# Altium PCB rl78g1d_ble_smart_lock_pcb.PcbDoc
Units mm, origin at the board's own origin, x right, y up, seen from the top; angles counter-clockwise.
Board outline 77.6 x 48.9 mm, 2 copper layers (Top Layer, Bottom Layer); 55 components, 39 nets, 175 pads, 18 vias.
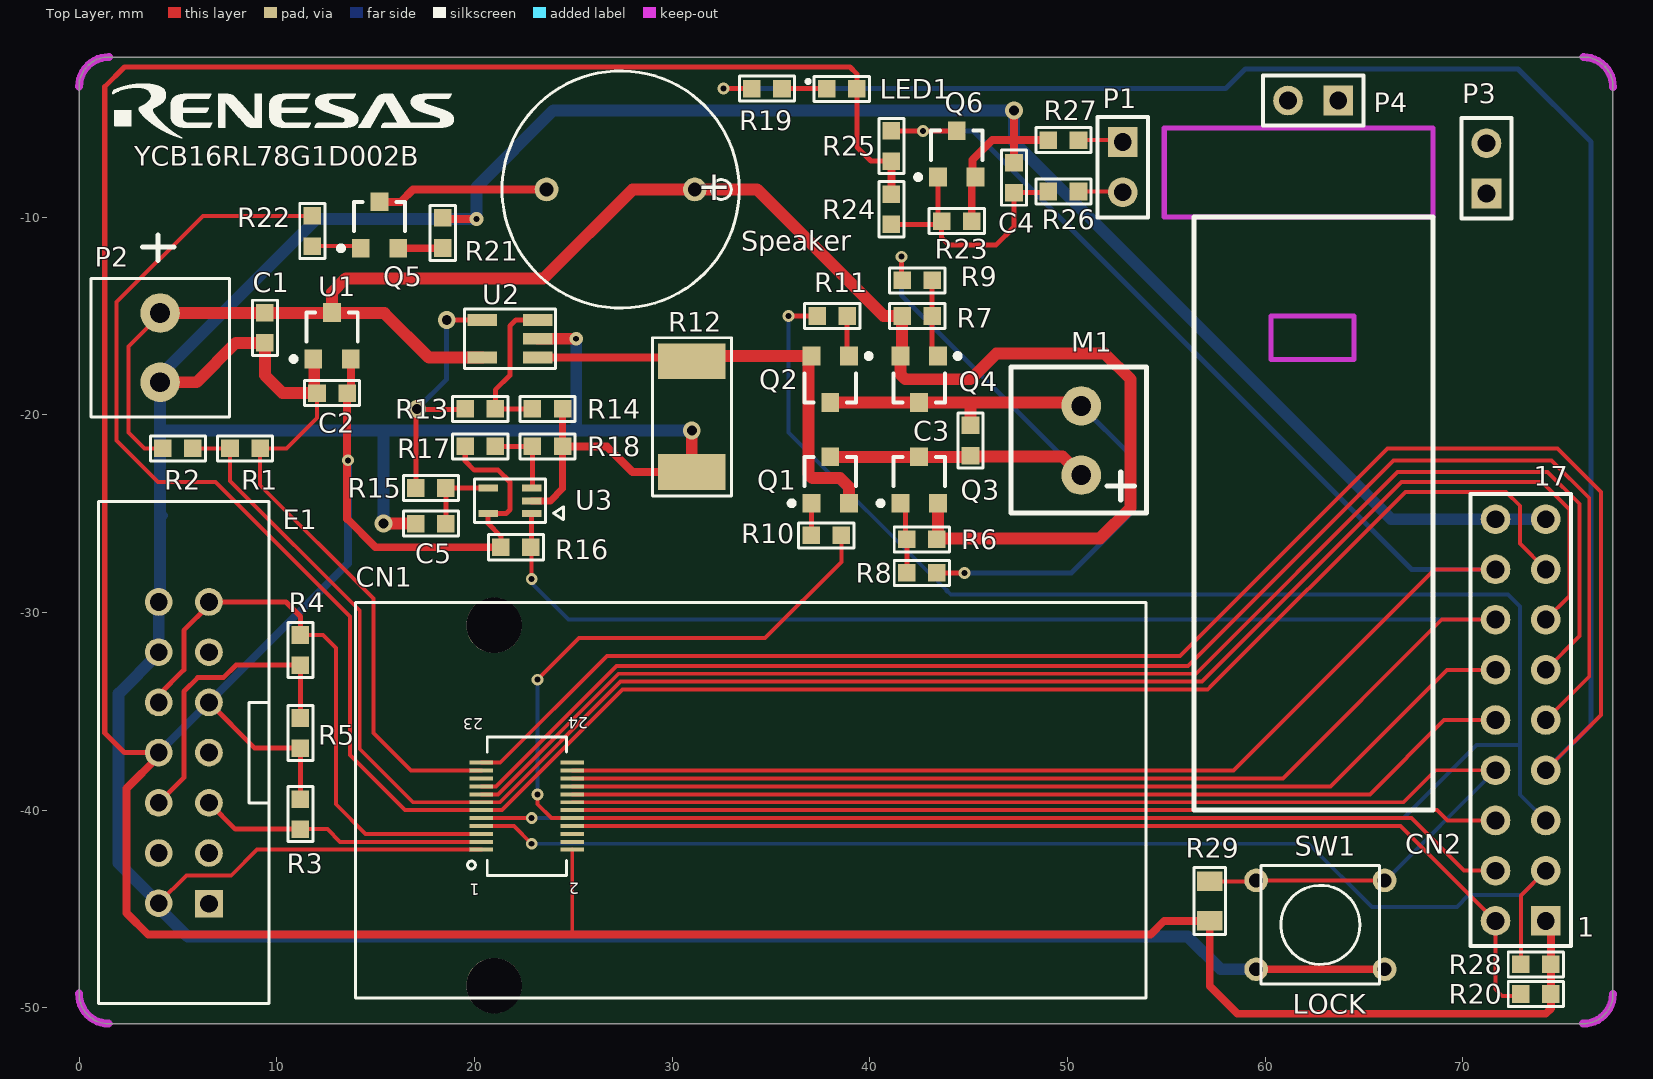
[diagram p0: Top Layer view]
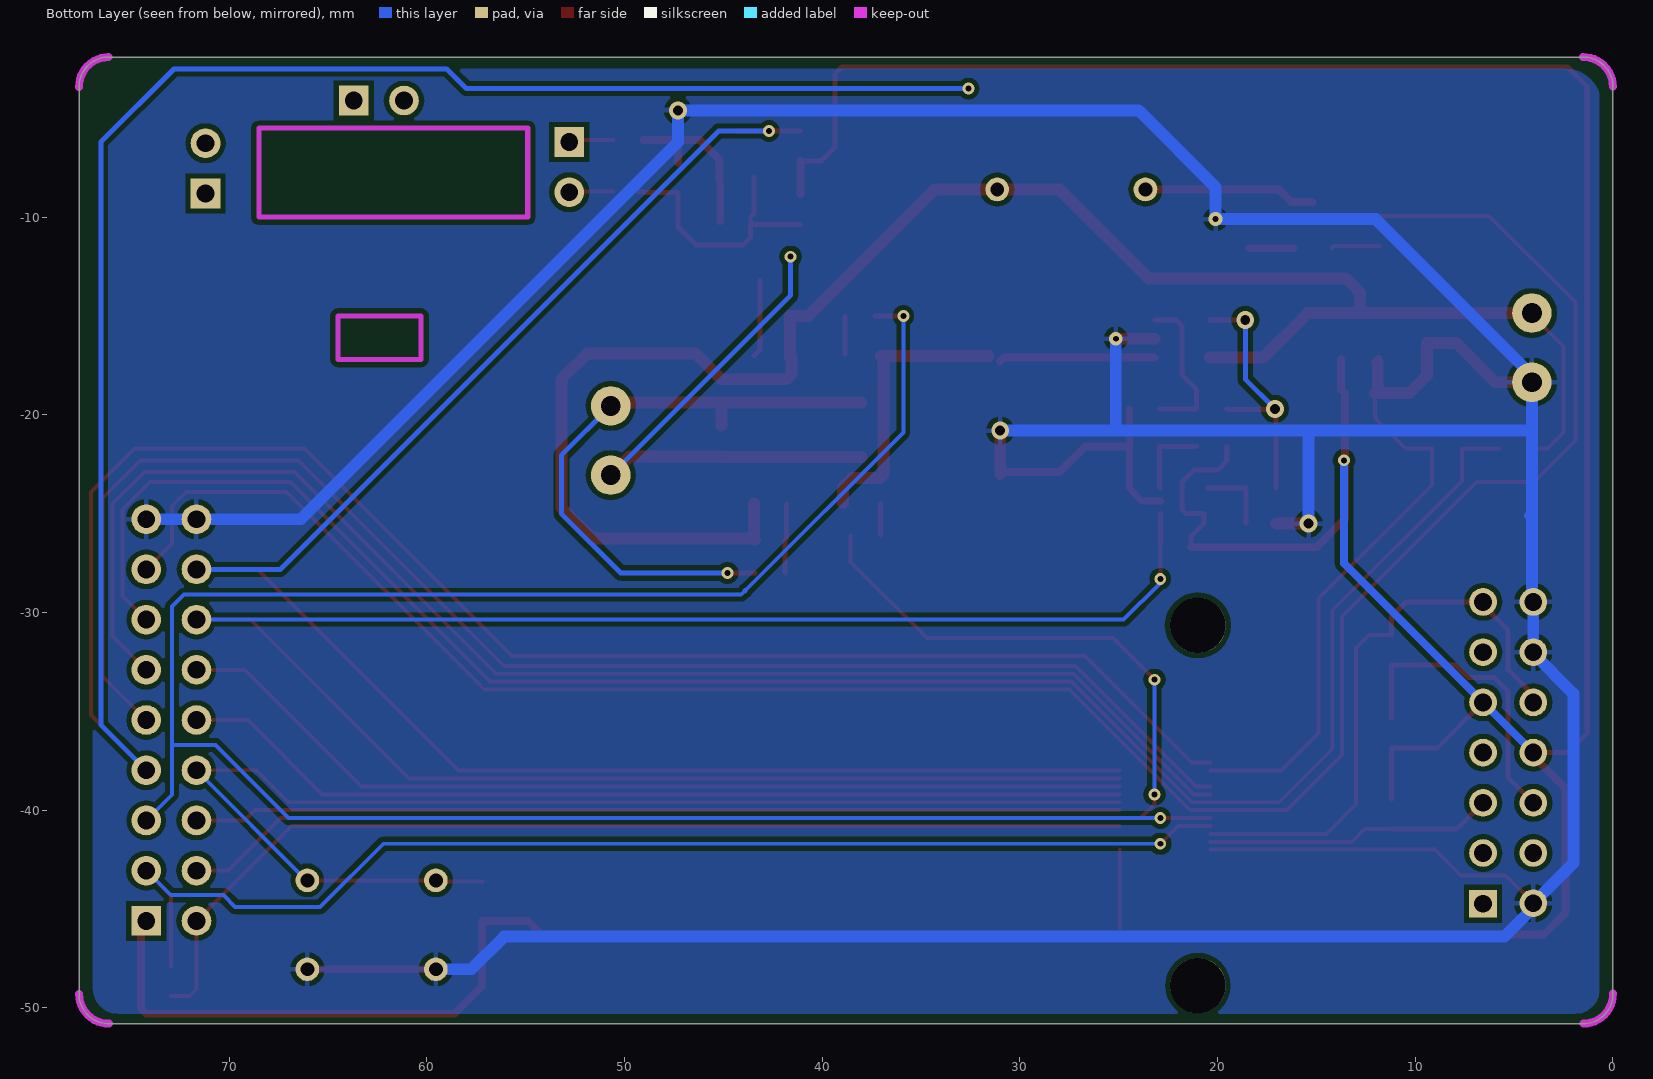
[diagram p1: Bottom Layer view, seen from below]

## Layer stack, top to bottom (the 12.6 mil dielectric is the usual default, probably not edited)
Top Layer: signal copper 0.0356
Dielectric: dielectric 0.32, FR-4, Dk 4.8
Bottom Layer: signal copper 0.0356

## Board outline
1.5,-50.8 cw(c1.5,-49.3) 0,-49.277 0,-3.4 cw(c1.5,-3.4) 1.523,-1.9 76.1,-1.9 cw(c76.1,-3.4) 77.6,-3.423 77.6,-3.4 77.6,-49.3 cw(c76.1,-49.3) 76.077,-50.8

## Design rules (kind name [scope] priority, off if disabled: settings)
Clearance [All] p1: gap=0.254
ComponentClearance [All] p1: gap=0.254 collisioncheckmode=3 verticalgap=0.254
PolygonConnect [All] p1: connectstyle=Relief reliefconductorwidth=0.254 reliefentries=4 polygonreliefangle="90 Angle"
RoutingVias [All] p1: holewidth=0.711 width=1.27 viastyle="Through Hole" minholewidth=0.711 minwidth=1.27 maxholewidth=0.711 maxwidth=1.27
SolderMaskExpansion [All] p1: expansion=0.102
TestPointUsage [All] p1: valid=0 allowmultiple=FALSE
Testpoint [All] p1: side=15 testpointundercomponent=TRUE minsize=1.016 maxsize=2.54 preferedsize=1.524 minholesize=0 maxholesize=1.016 preferedholesize=0.813 testpointgrid=0.025 style=1023 order=0123456789
Width [All] p1: maxlimit=1 minlimit=0.2 preferedwidth=0.254 minimp=50.000000 maximp=50.000000 favimp=50.000000
18 further rules are at their usual default settings.

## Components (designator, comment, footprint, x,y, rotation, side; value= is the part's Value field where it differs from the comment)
C1 "1uF" 0603 9.4,-15.6 r270 top
C2 "1uF" 0603 12.8,-18.9 r180 top
C3 "100nF" 0603 45.1,-21.3 r90 top
C4 "100nF" 0603 47.3,-8 r270 top
C5 "100nF" 0603 17.8,-25.5 r0 top
CN1 "Coaxial connector" "CRS5001 - 24" 14,-49.5 r180 top
CN2 "Header 9X2" HDR2X9 74.2,-45.6 r90 top
E1 "J1" "E8 Connect - duplicate" 5.3,-37.1 r180 top
LED1 "R" "LED 0603" 38.586,-3.51 r180 top
M1 "Motor" "CON-2 D" 50.7,-21.3 r90 top
P1 "LOCK" HDR1X2 52.8,-6.2 r270 top
P2 "BAT AAAx3" "CON-2 D" 4.1,-16.6 r270 top
P3 "Baffle" HDR1X2 71.2,-8.8 r90 top
P4 "Baffle" HDR1X2 63.7,-4.1 r180 top
Q1 "S8050" SOT23A 38,-23.3 r0 top
Q2 "S8050" SOT23A 38,-18.2 r180 top
Q3 "S8550" SOT23A 42.5,-23.3 r0 top
Q4 "S8550" SOT23A 42.5,-18.2 r180 top
Q5 "S8050" SOT23A 15.2,-10.4 r0 top
Q6 "S8050" SOT23A 44.4,-6.8 r0 top
R1 "100K" 0603 8.4,-21.7 r0 top
R2 "100K" 0603 5,-21.7 r0 top
R3 "1K" 0603 11.2,-40.2 r270 top
R4 "10K" 0603 11.2,-31.9 r270 top
R5 "1K" 0603 11.2,-36.1 r270 top
R6 "4.7K" 0603 42.638,-26.3 r0 top
R7 "4.7K" 0603 42.4,-15 r180 top
R8 "470" 0603 42.638,-28 r180 top
R9 "470" 0603 42.4,-13.2 r180 top
R10 "470" 0603 37.8,-26.1 r180 top
R11 "470" 0603 38.1,-15 r180 top
R12 "1.5R" 2512 31,-20.1 r90 top
R13 "10K" 0603 20.3,-19.7 r180 top
R14 "1K" 0603 23.7,-19.7 r180 top
R15 "1K" 0603 17.8,-23.7 r0 top
R16 "1K" 0603 22.1,-26.7 r180 top
R17 "100K" 0603 20.3,-21.6 r0 top
R18 "100K" 0603 23.7,-21.6 r0 top
R19 "1K" 0603 34.8,-3.5 r180 top
R20 "1K" 0603 73.7,-49.3 r180 top
R21 "100" 0603 18.4,-10.8 r270 top
R22 "10K" 0603 11.8,-10.7 r90 top
R23 "1M" 0603 44.4,-10.2 r0 top
R24 "470K" 0603 41.1,-9.6 r270 top
R25 "2.2M" 0603 41.1,-6.4 r90 top
R26 "10K" 0603 49.8,-8.7 r0 top
R27 "100" 0603 49.8,-6.1 r180 top
R28 "1K" 0603 73.7,-47.8 r0 top
R29 "10K" 0805 57.2,-44.6 r90 top
Speaker "Buzzer" "BUZZER A" 27.4,-8.6 r180 top
SW1 "LOCK" "KEY B (6 X 6)" 62.8,-45.8 r180 top
U1 "XC6206-3.3V" SOT23A 12.8,-16 r0 top
U2 "LM321" SOT-23-5 23.2,-17.1 r180 top
U3 "NCX2202" "SC-70 5" 22.9,-25 r180 top
YCB16RL78G1D002B "Comment" "RENESAS LOGO" 9.9,-4.8 r0 top

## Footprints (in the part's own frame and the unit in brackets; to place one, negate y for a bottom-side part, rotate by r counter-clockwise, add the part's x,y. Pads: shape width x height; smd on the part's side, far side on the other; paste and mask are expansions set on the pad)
0603 [mil]
  rect 35x35 smd: 1(-30,0) 2(30,0)
  silkscreen extent -55,-25 55,25
0805 [mm]
  rect 1x1.3 smd: 1(-1,0) 2(1,0)
  silkscreen extent -1.7,-0.8 1.7,0.8
2512 [mm]
  rect 1.8x3.4 smd: 1(-2.794,0) 2(2.806,0)
  silkscreen extent -4,-2 4,2
"BUZZER A" [mm]
  round 1.2 hole 0.7: 1(-3.75,0) 2(3.75,0)
  silkscreen extent -6,-6 6,6
"CON-2 D" [mm]
  round 2 hole 1: 1(-1.75,0) 2(1.75,0)
  silkscreen extent -3.65,-3.3 3.71,3.56
"CRS5001 - 24" [mm]
  round 2.8 hole 2.8: 0(-7,-0.625) 0(-7,-18.85)
  rect 1.2x0.2 smd: 1(-6.35,-7.5) 2(-10.95,-7.5) 3(-6.35,-7.9) 4(-10.95,-7.9) 5(-6.35,-8.3) 6(-10.95,-8.3) 7(-6.35,-8.7) 8(-10.95,-8.7) 9(-6.35,-9.1) 10(-10.95,-9.1) 11(-6.35,-9.5) 12(-10.95,-9.5) 13(-6.35,-9.9) 14(-10.95,-9.9) 15(-6.35,-10.3) 16(-10.95,-10.3) 17(-6.35,-10.7) 18(-10.95,-10.7) 19(-6.35,-11.1) 20(-10.95,-11.1) 21(-6.35,-11.5) 22(-10.95,-11.5) 23(-6.35,-11.9) 24(-10.95,-11.9)
  silkscreen extent -39.98,-20 0.03,0
"E8 Connect - duplicate" [mm]
  rect 1.4x1.4 hole 0.9: 1(-1.27,7.633)
  round 1.4 hole 0.9: 2(1.27,7.607) 3(-1.27,5.067) 4(1.27,5.067) 5(-1.27,2.527) 6(1.27,2.527) 7(-1.27,-0.013) 8(1.27,-0.013) 9(-1.27,-2.553) 10(1.27,-2.553) 11(-1.27,-5.093) 12(1.27,-5.093) 13(-1.27,-7.633) 14(1.27,-7.633)
  silkscreen extent -4.32,-12.71 4.32,12.69
HDR1X2 [mm] "Connector; Header; 2 Position"
  rect 1.5x1.5 hole 0.9: 1(0,0)
  round 1.5 hole 0.9: 2(2.54,0)
  silkscreen extent -1.27,-1.27 3.81,1.27
HDR2X9 [mm] "Connector; Header; 9x2 Position"
  rect 1.5x1.5 hole 0.9: 1(0,0)
  round 1.5 hole 0.9: 2(0,2.54) 3(2.54,0) 4(2.54,2.54) 5(5.08,0) 6(5.08,2.54) 7(7.62,0) 8(7.62,2.54) 9(10.16,0) 10(10.16,2.54) 11(12.7,0) 12(12.7,2.54) 13(15.24,0) 14(15.24,2.54) 15(17.78,0) 16(17.78,2.54) 17(20.32,0) 18(20.32,2.54)
  silkscreen extent -1.27,-1.27 21.59,3.81
"KEY B (6 X 6)" [mm]
  round 1.2 hole 0.7: 1(-3.25,2.25) 2(-3.25,-2.25) 3(3.25,-2.25) 4(3.25,2.25)
  silkscreen extent -3,-3 3,3
"LED 0603" [mil]
  rect 35x35 smd: A(-30,0) K(30,0)
  silkscreen extent -55,-25 69,25
"RENESAS LOGO" [mm]
  silkscreen extent -8.18,-1.18 9.06,1.54
"SC-70 5" [mm]
  rect 1x0.35 smd: 1(0,0) 2(0,-0.65) 3(0,-1.3) 4(2.2,-1.3) 5(2.2,0)
  silkscreen extent -1.6,-1.75 2.9,0.45
SOT23A [mm] "SOT-23; 3 Leads; Body 3.0 x 2.5 mm, inc. leads (LxW max)"
  rect 0.9x0.95 smd: 1(-0.95,-1.175) 2(0.95,-1.175) 3(0,1.175)
  silkscreen extent -2.07,-1.3 1.3,1.18
SOT-23-5 [mm]
  rect 1.5x0.6 smd: 1(0,0) 2(0,-0.95) 3(0,-1.9) 4(2.8,-1.9) 5(2.8,0)
  silkscreen extent -0.9,-2.45 3.7,0.55

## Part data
C1 C2 C3 C4 C5: library part CAP
CN2: "Header, 9-Pin, Dual row"
E1: library part E1
LED1: library part LED2, "Typical RED, GREEN, YELLOW, AMBER GaAs LED"
P1: "Header, 4-Pin"
P2: library part "Cell Battery", "Header, 4-Pin"
P3 P4: library part Header-2, "Header, 4-Pin"
R1 R2 R3 R4 R5 R6 R7 R8 R9 R10 R11 R12 R13 R14 R15 R16 R17 R18 R19 R20 R21 R22 R23 R24 R25 R26 R27 R28 R29: library part RES
Speaker: library part SPEAKER
SW1: library part SW-PB, "Switch"
U1: library part XC6206

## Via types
v1: diameter 0.6, hole 0.3, Top Layer to Bottom Layer, 11 vias
v2: diameter 0.9, hole 0.5, Top Layer to Bottom Layer, 5 vias
v3: diameter 0.7, hole 0.3, Top Layer to Bottom Layer, 2 vias

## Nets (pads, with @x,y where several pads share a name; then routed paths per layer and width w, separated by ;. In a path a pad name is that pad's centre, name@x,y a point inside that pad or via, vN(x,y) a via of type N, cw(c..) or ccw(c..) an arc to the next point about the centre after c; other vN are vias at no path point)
3.3V: C2.1 CN1.2 CN2.1 E1.8 E1.9 LED1.A R3.1 R5.2 R16.2 R17.1 R20.1 R24.1 R25.1 R28.2 R29.1 U1.2 U3.5 | length 227.3
  Top Layer w0.2: CN1.2 24.95,-46.25 25,-46.3
  Top Layer w0.254: E1.8 2.287,-37.087 1.3,-36.1 1.3,-3.4 2.3,-2.4 39,-2.4 39.348,-2.748 39.348,-6.448 40.062,-7.162 R25.1 ; E1.9 8.885,-36.862 R5.2 R3.1 ; R17.1 19.538,-22.338 20,-22.8 21.2,-22.8 21.8,-23.4 21.8,-24.8 21.6,-25 U3.5 20.7,-25.5 21.338,-26.138 R16.2
  Top Layer w0.4: E1.8 4.03,-37.27 2.4,-38.9 2.4,-45.2 3.5,-46.3 54.2,-46.3 54.9,-45.6 R29.1 57.2,-48.9 58.6,-50.3 74.2,-50.3 74.462,-50.038 CN2.1@74.462,-45.638 ; C2.1 13.562,-25.262 15,-26.7 R16.2 ; C2.1@13.75,-18.712 U1.2 ; R24.1 R25.1
  Bottom Layer w0.4: E1.8 13.6,-27.517 v1(13.6,-22.3)
4.5V: C1.1 P2.1 Q3.2 Q4.2 R2.1 R6.2 R7.2 Speaker.1 U1.3 U2.5 | length 95.3
  Top Layer w0.2: P2.1@4.2,-14.85 2.5,-16.55 2.5,-20.9 3.3,-21.7 R2.1
  Top Layer w0.6: P2.1@4.2,-14.85 15.45,-14.85 17.7,-17.1 U2.5 ; U1.3@12.775,-14.85 U1.3 12.8,-13.8 13.5,-13.1 23.5,-13.1 28,-8.6 34.3,-8.6 40.7,-15 R7.2 Q4.2@41.638,-17.138 ; Q4.2 41.55,-17.95 41.8,-18.2 45.1,-18.2 46.4,-16.9 51.9,-16.9 53.2,-18.2 53.2,-24.7 51.65,-26.25 R6.2@43.45,-26.25 ; R6.2 R6.2@43.45,-26.25 ; Q3.2 R6.2@43.45,-26.25
AD1: CN1.13 CN2.13 R1.1 R2.2 | length 95.5
  Top Layer w0.2: R2.2 R1.1 7.638,-23.338 14.2,-29.9 14.2,-36.9 16.9,-39.6 21.3,-39.6 27.4,-33.5 56.8,-33.5 57.3,-33 66.9,-23.4 74,-23.4 75.4,-24.8 75.4,-29.16 CN2.13
BUZZER: CN1.11 CN2.15 R22.2 | length 112.3
  Top Layer w0.2: R22.2 6.262,-9.938 1.9,-14.3 1.9,-21.3 4,-23.4 6.9,-23.4 13.7,-30.2 13.7,-37.2 16.5,-40 21.4,-40 27.5,-33.9 57.1,-33.9 57.3,-33.7 67.1,-23.9 72.2,-23.9 72.9,-24.6 72.9,-26.52 CN2.15
CCW: CN1.10 CN2.4 R10.1 | length 75.3
  Top Layer w0.2: v1(23.2,-39.2) 23.2,-39.7 23.9,-40.4 67.4,-40.4 70.06,-43.06 CN2.4 ; v1(23.2,-33.4) 25.3,-31.3 34.7,-31.3 38.562,-27.438 R10.1
  Bottom Layer w0.2: v1(23.2,-39.2) v1(23.2,-33.4)
CN1: CN1.15 CN2.11 | length 72.1
  Top Layer w0.2: CN1.15 21.2,-39.2 27.3,-33.1 56.5,-33.1 66.7,-22.9 74.3,-22.9 75.9,-24.5 75.9,-31.2 CN2.11
CN2: CN1.17 CN2.9 | length 75.8
  Top Layer w0.2: CN1.17 21.1,-38.8 27.2,-32.7 56.1,-32.7 66.5,-22.3 74.5,-22.3 76.4,-24.2 76.4,-33.24 CN2.9
CW: CN1.9 CN2.5 R11.2 | length 113.4
  Top Layer w0.2: CN1.9 v1(22.9,-40.4)
  Top Layer w0.254: v1(35.9,-15) R11.2
  Bottom Layer w0.2: v1(22.9,-40.4) 67,-40.4 70.7,-36.7 72.9,-36.7 ; v1(35.9,-15) 35.9,-20.9 43.9,-28.9 44.1,-29.1 72.3,-29.1 72.9,-29.7 72.9,-39.22 CN2.5
GND: C1.2 C2.2 C4.1 C5.1 CN1.1 CN1.21 CN2.17 CN2.18 E1.2 E1.12 E1.14 P2.2 Q6.2 R1.2 R12.1 R14.1 R18.2 R21.1 R23.2 R27.2 SW1.1 SW1.4 U1.1 U2.2 U3.2 | length 302.8
  Top Layer w0.2: E1.2 5.437,-43.3 7.7,-43.3 9,-42 CN1.1 ; C2.2 12.038,-20.162 10.5,-21.7 R1.2 9.162,-23.562 14.9,-29.3 14.9,-36.1 16.8,-38 CN1.21
  Top Layer w0.35: U3.2 23.85,-24.35 24.462,-23.738 R14.1
  Top Layer w0.4: U1.1 U1.1@12.038,-17.363 ; R21.1@18.462,-10.1 v3(20.1,-10.1) ; R18.2 26.7,-21.6 27.994,-22.894 R12.1 ; R23.2 45.162,-8.163 45.2,-8.125 45.2,-7.1 46.2,-6.1 R27.2 ; C4.1 47.3,-6.1 ; v2(47.3,-4.6) 47.3,-6 47.4,-6.1 ; SW1.4 SW1.1
  Top Layer w0.6: P2.2@4.2,-18.35 5.95,-18.35 7.938,-16.362 C1.2 9.4,-18 10.3,-18.9 C2.2 ; C2.2@11.9,-18.9 U1.1@11.9,-17.301 ; v2(15.4,-25.5) C5.1 ; U2.2 v3(25.15,-16.15) ; R12.1@31,-23 v2(31,-20.8)
  Bottom Layer w0.4: 4.1,-25.3 4.3,-25.1 ; P2.2 P2.2@4.1,-18
  Bottom Layer w0.6: 4.1,-20.7 4.2,-20.8 v2(31,-20.8) ; P2.2 4.1,-29.397 E1.14 4.03,-32.07 2,-34.1 2,-42.677 E1.2 4.03,-44.93 5.5,-46.4 56.1,-46.4 57.75,-48.05 SW1.4 ; P2.2@4.1,-18 12,-10.1 v3(20.1,-10.1) 20.1,-8.5 24,-4.6 v2@47.4,-4.6 ; v2(15.4,-25.5) 15.4,-20.8 ; 25.15,-20.75 v3(25.15,-16.15) ; v2(47.3,-4.6) 47.3,-6.2 66.38,-25.28 CN2.17
IN-: C5.2 R15.2 U3.4 | length 3.7
  Top Layer w0.254: C5.2 R15.2 U3.4@20.5,-23.7
LED1: CN1.23 CN2.7 R19.2 | length 159.4
  Top Layer w0.2: CN1.23 21.3,-37.6 26.7,-32.2 55.7,-32.2 64.7,-23.2 66.2,-21.7 74.8,-21.7 77,-23.9 77,-35.18 CN2.7
  Top Layer w0.254: v1(32.6,-3.5) R19.2
  Bottom Layer w0.254: v1(32.6,-3.5) 58,-3.5 59,-2.5 72.8,-2.5 76.5,-6.2 76.5,-35.68 CN2.7
M+: C3.1 M1.1 Q1.3 Q3.3 R9.2 | length 29.1
  Top Layer w0.254: R9.2@41.6,-13.162 v1(41.6,-12)
  Top Layer w0.6: Q1.3 45.037,-22.125 45.062,-22.1 49.75,-22.1 M1.1
  Bottom Layer w0.254: v1(41.6,-12) 41.6,-13.95 M1.1
M-: C3.2 M1.2 Q2.3 Q4.3 R8.1 | length 31.5
  Top Layer w0.254: R8.1 v1(44.8,-28)
  Top Layer w0.6: Q2.3 50.525,-19.375 M1.2 ; C3.2 45.1,-19.375
  Bottom Layer w0.254: v1(44.8,-28) 50.2,-28 53.2,-25 53.2,-22.05 M1.2
NetC4_2: C4.2 Q6.1 R23.1 R24.2 R26.1 | length 13.5
  Top Layer w0.254: R24.2 R23.1@43.662,-10.362 ; Q6.1 43.45,-9.812 R23.1@43.638,-10 ; R23.1 43.638,-11.038 44,-11.4 46.4,-11.4 47.3,-10.5 C4.2 48.976,-8.762 R26.1 R26.1@49.338,-8.7
NetE1_6: E1.6 R4.2 R5.1 | length 15.3
  Top Layer w0.254: E1.6 5.3,-38.357 5.3,-34 6,-33.3 7.3,-33.3 7.938,-32.662 R4.2 R5.1
NetLED1_K: LED1.K R19.1 | length 2.3
  Top Layer w0.254: R19.1 LED1.K@37.814,-3.5
NetP1_1: P1.1 R27.1 | length 2.1
  Top Layer w0.2: R27.1 P1.1@52.7,-6.1
NetP1_2: P1.2 R26.2 | length 2.2
  Top Layer w0.2: R26.2 P1.2@52.76,-8.7
NetQ1_1: Q1.1 R10.2 | length 1.6
  Top Layer w0.254: R10.2@37.05,-26.088 Q1.1
NetQ2_1: Q2.1 R11.1 | length 1.9
  Top Layer w0.254: Q2.1@38.862,-16.937 R11.1
NetQ3_1: Q3.1 R6.1 R8.2 | length 3.5
  Top Layer w0.254: Q3.1@41.8,-24.5 41.8,-26.224 R6.1 R8.2
NetQ4_1: Q4.1 R7.1 R9.1 | length 3.9
  Top Layer w0.254: R9.1 43.162,-16.737 Q4.1
NetQ5_1: Q5.1 R22.1 | length 2.5
  Top Layer w0.2: R22.1 14.137,-11.462 Q5.1
NetQ5_2: Q5.2 R21.2 | length 2.2
  Top Layer w0.4: Q5.2 R21.2@18.387,-11.575
NetQ5_3: Q5.3 Speaker.2 | length 8.7
  Top Layer w0.4: Q5.3 16.275,-9.225 16.9,-8.6 Speaker.2
NetR13_1: R13.1 R14.2 U2.3 | length 7.9
  Top Layer w0.254: R14.2 R13.1 21.062,-18.738 21.8,-18 21.8,-15.5 22.1,-15.2 U2.3
NetR13_2: R13.2 R15.1 U2.4 | length 13.4
  Top Layer w0.254: R15.1 17.038,-19.762 v2(17.1,-19.7) ; v2@17.138,-19.738 19.5,-19.738 R13.2 ; v2(18.6,-15.2) U2.4
  Bottom Layer w0.254: v2(17.1,-19.7) 18.6,-18.2 v2(18.6,-15.2)
NetR17_2: R17.2 R18.1 U3.3 | length 4
  Top Layer w0.254: R17.2 R18.1 22.938,-23.662 U3.3
P10: CN1.14 CN2.8 R29.2 SW1.2 SW1.3 | length 64.1
  Top Layer w0.2: CN1.14 67,-39.6 68.62,-37.98 CN2.8 ; R29.2 SW1.3@59.5,-43.6 ; SW1.3 SW1.2
  Bottom Layer w0.2: SW1.2 66.09,-43.55 CN2.8
P12: CN1.12 CN2.6 | length 46.9
  Top Layer w0.2: CN1.12 68.7,-40 69.22,-40.52 CN2.6
P16/INTP5: CN1.20 CN2.14 R16.1 U3.1 | length 103.1
  Top Layer w0.2: v1(22.9,-28.3) R16.1@22.9,-26.5 ; CN1.20 60.9,-38.4 68.94,-30.36 CN2.14
  Top Layer w0.254: R16.1@22.9,-26.5 U3.1
  Bottom Layer w0.2: v1(22.9,-28.3) 22.9,-28.5 24.76,-30.36 CN2.14
P22: CN1.16 CN2.10 | length 48.3
  Top Layer w0.2: CN1.16 65.3,-39.2 69.06,-35.44 CN2.10
P23: CN1.18 CN2.12 | length 49.2
  Top Layer w0.2: CN1.18 63.3,-38.8 69.2,-32.9 CN2.12
P30/INTP3: CN1.22 CN2.16 Q6.3 R25.2 | length 92.4
  Top Layer w0.2: CN1.22 58.4,-38 68.58,-27.82 CN2.16
  Top Layer w0.254: R25.2 Q6.3@44.387,-5.638
  Bottom Layer w0.254: v1(42.7,-5.638) 45.238,-5.638 67.42,-27.82 CN2.16
P40/TOOL0: CN1.3 E1.5 R3.2 | length 14.6
  Top Layer w0.2: R3.2 12.562,-40.962 13.2,-41.6 CN1.3
  Top Layer w0.254: E1.5 7.905,-40.962 R3.2
P60: CN1.7 CN2.3 R28.1 | length 61.7
  Top Layer w0.2: CN1.7 22,-40.8 v1(22.9,-41.7) ; R28.1@72.938,-47.9 72.938,-44.322 CN2.3
  Bottom Layer w0.2: v1(22.9,-41.7) 62.2,-41.7 65.4,-44.9 69.7,-44.9 70.3,-44.3 72.96,-44.3 CN2.3
P61: CN1.8 CN2.2 R20.2 | length 53.6
  Top Layer w0.2: CN1.8 66.86,-40.8 CN2.2 71.66,-49.06 72,-49.4 R20.2@72.938,-49.4
RESET: CN1.5 E1.10 E1.13 R4.1 | length 29.9
  Top Layer w0.2: R4.1 12.338,-31.138 13,-31.8 13,-39.7 14.5,-41.2 CN1.5
  Top Layer w0.254: E1.10 4.03,-34.17 5.3,-32.9 5.3,-30.9 6.57,-29.63 E1.13 10.467,-29.467 11.2,-30.2 R4.1
SENSE: Q1.2 Q2.2 R12.2 U2.1 | length 22.5
  Top Layer w0.4: U2.1 30.806,-17.1 R12.2
  Top Layer w0.6: R12.2@31.575,-17.025 Q2.2 36.9,-17.175 36.9,-23 37.1,-23.2 38.5,-23.2 38.95,-23.65 Q1.2
pads on no net: CN1.0 CN1.4 CN1.6 CN1.19 CN1.24 E1.1 E1.3 E1.4 E1.7 E1.11 P3.1 P3.2 P4.1 P4.2

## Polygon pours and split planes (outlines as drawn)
GND on Bottom Layer "Top Overlay-No Net" (solid, remove dead copper): 0.6,-5.1 0.6,-4.3 cw(c2.4,-4.3) 2.4,-2.5 75.3,-2.5 cw(c75.3,-4.1) 76.9,-4.1 76.9,-49 cw(c75.6,-49) 75.6,-50.3 1.9,-50.3 cw(c1.9,-49.1) 0.7,-49.1 0.7,-3.8

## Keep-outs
Keep-Out Layer:
  lines w0.254: 54.9,-10 68.5,-10 68.5,-5.5 54.9,-5.5 54.9,-10 ; 60.3,-17.2 64.5,-17.2 64.5,-15 60.3,-15 60.3,-17.2
  lines w0.4: 0,-49.277 ccw(c1.5,-49.3) 1.5,-50.8 ; 0,-3.4 cw(c1.5,-3.4) 1.523,-1.9 ; 76.077,-50.8 ccw(c76.1,-49.3) 77.6,-49.3 ; 76.1,-1.9 cw(c76.1,-3.4) 77.6,-3.423

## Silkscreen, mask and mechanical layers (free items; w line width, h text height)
Top Overlay:
  lines w0.254: 3.2,-11.5 4.8,-11.5 ; 4,-12.2 4,-10.9 ; 52,-23.6 53.4,-23.6 ; 52.7,-24.3 52.7,-22.9 ; 56.4,-10 56.4,-40 68.4,-40 ; 56.424,-10 68.424,-10 ; 68.489,-40 68.489,-10
Mechanical 1:
  lines w0.254: -2.654,-49.376 -2.146,-50.9 ; -2.654,-3.424 -2.146,-1.9 ; -2.4,-50.9 -1.892,-50.9 ; -2.4,-1.9 -1.892,-1.9 ; -2.146,-31.504 -2.146,-50.9 ; -2.146,-21.296 -2.146,-1.9 ; -1.638,-49.376 -2.146,-50.9 ; -1.638,-3.424 -2.146,-1.9 ; 0,-0.24 0,0.268 ; 1.524,-0.494 0,0.014 ; 1.524,0.522 0,0.014 ; 33.896,0.014 0,0.014 ; 44.104,0.014 78,0.014 ; 76.476,-0.494 78,0.014 ; 76.476,0.522 78,0.014 ; 78,-0.24 78,0.268
  lines w0.4: 0,-49.277 0,-3.4 ; 1.5,-50.8 76.077,-50.8 ; 1.523,-1.9 76.1,-1.9 ; 77.6,-49.3 77.6,-3.4
  text "78 (mm)" at 34.15,-0.9 h1.52
  text "49 (mm)" at -1.232,-31.25 h1.52 r90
